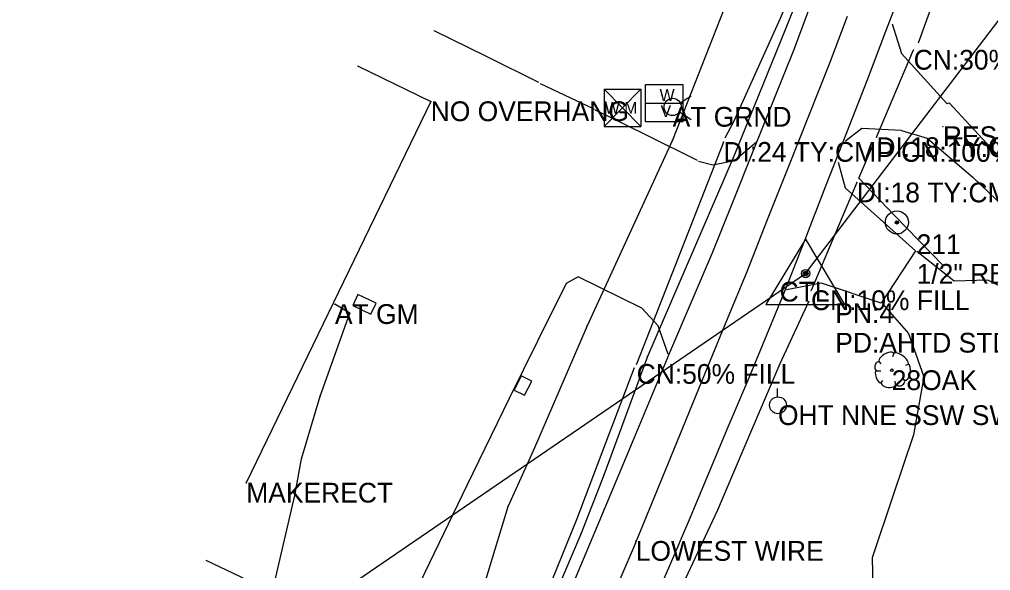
# Model space of a CAD drawing. Extents: x 997398 to 1003416, y 334596 to 337085.
# Drawn here: x 999358.1 to 999603.8, y 336202.6 to 336342 of the extents above; entities that cross this region are included whole.
import ezdxf

# ---------------------------------------------------------------- set-up
doc = ezdxf.new("R2010")
doc.units = 0
for name, color, linetype in [('Default', 7, 'Continuous'), ('S_BUILDING', 7, 'Continuous'), ('S_BUILDING_ANNOT', 7, 'Continuous'), ('S_CURB', 7, 'Continuous'), ('S_DITCHLINE', 7, 'Continuous'), ('S_DRG_PT_SYM', 7, 'Continuous'), ('S_DRIVEWAY', 7, 'Continuous'), ('S_EDGE_CONCRETE', 7, 'Continuous'), ('S_EDGE_PAVEMENT', 7, 'Continuous'), ('S_ELECTRIC_UTILITIES_ANNOT', 7, 'Continuous'), ('S_FIBER_OPTIC_CABLE', 7, 'Continuous'), ('S_GAS_UTILITIES', 7, 'Continuous'), ('S_GAS_UTILITIES_ANNOT', 7, 'Continuous'), ('S_GRAVEL_ROAD', 7, 'Continuous'), ('S_GRD_PT_SYM', 7, 'Continuous'), ('S_IRON_PIN', 7, 'Continuous'), ('S_IRON_PIN_ANNOT', 7, 'Continuous'), ('S_MSC_PT_SYM', 7, 'Continuous'), ('S_PAVEMENT_CROWN', 7, 'Continuous'), ('S_PRIMARY_CTL', 7, 'Continuous'), ('S_PRIMARY_CTL_ANNOT', 7, 'Continuous'), ('S_SIDE_DRAIN', 7, 'Continuous'), ('S_SIDE_DRAIN_ANNOT', 7, 'Continuous'), ('S_STR_PT_SYM', 7, 'Continuous'), ('S_SURVEY_TEXT_ANNOT', 7, 'Continuous'), ('S_TREE', 7, 'Continuous'), ('S_TREE_ANNOT', 7, 'Continuous'), ('S_UTILITY_POLE', 7, 'Continuous'), ('S_UTILITY_POLE_ANNOT', 7, 'Continuous'), ('S_UTL_PT_SYM', 7, 'Continuous'), ('S_WATER_UTILITIES', 7, 'Continuous'), ('S_WATER_UTILITIES_ANNOT', 7, 'Continuous')]:
    doc.layers.add(name, color=color, linetype=linetype)

msp = doc.modelspace()

# ---------------------------------------------------------------- linework, layer by layer
at = {"layer": 'Default'}
for p, q in [((999557.02, 336277.74), (999737.12, 336514.03)), ((998964.3, 335872.43), (999557.02, 336277.74))]:
    msp.add_line(p, q, dxfattribs=at)
at = {"layer": 'S_BUILDING'}
for p, q in [((999443.8, 336330.18), (999462.16, 336321.31)), ((999462.16, 336321.31), (999415.5, 336224.79))]:
    msp.add_line(p, q, dxfattribs=at)
at = {"layer": 'S_CURB'}
for points in [[(999489.52, 336326.12), (999476.27, 336332.64), (999463.01, 336339.16)], [(999529.68, 336306.31), (999527.62, 336307.32), (999510.08, 336316.03), (999504.7, 336318.64), (999503.71, 336319.2)]]:
    msp.add_lwpolyline(points, dxfattribs=at)
at = {"layer": 'S_DITCHLINE'}
for points in [[(999585.56, 336336.15), (999591.87, 336353.69), (999598.19, 336371.23), (999604.53, 336388.73), (999609.68, 336403.37), (999615.75, 336417.57), (999621.81, 336431.76), (999624.66, 336451.18), (999627.5, 336470.6), (999628.27, 336483.98), (999629.05, 336497.37), (999629.83, 336510.76), (999630.6, 336524.14), (999632.81, 336533.43), (999642.82, 336543.03), (999654.22, 336545.64), (999667.32, 336539.63), (999680.41, 336533.63)], [(999569.58, 336389.36), (999561, 336367.01), (999555.79, 336354.64), (999550.58, 336342.27), (999544.69, 336329.2), (999538.8, 336316.12), (999536.54, 336311.97)], [(999591.85, 336279.78), (999579.54, 336292.42), (999570.46, 336301.87), (999574.15, 336310.57)], [(999475.43, 336077.33), (999482.6, 336095.21), (999489.77, 336113.08), (999498.51, 336133.02), (999507.25, 336152.96), (999515.39, 336173.39), (999523.54, 336193.82), (999529.15, 336205.87), (999534.77, 336217.93), (999542.66, 336236.46), (999550.55, 336255), (999557.88, 336270.85)], [(999513.68, 336253.86), (999506.39, 336234.78), (999499.1, 336215.7), (999492.79, 336200.03), (999486.47, 336184.36), (999477.43, 336164.94), (999468.38, 336145.52)]]:
    msp.add_lwpolyline(points, dxfattribs=at)
at = {"layer": 'S_DRG_PT_SYM'}
for points in [[(999584.35, 336334.34), (999584.35, 336334.39), (999584.35, 336334.34), (999584.3, 336334.34), (999584.35, 336334.34), (999584.35, 336334.29), (999584.35, 336334.34), (999584.4, 336334.34)], [(999536.22, 336311.02), (999536.22, 336311.07), (999536.22, 336311.02), (999536.17, 336311.02), (999536.22, 336311.02), (999536.22, 336310.97), (999536.22, 336311.02), (999536.27, 336311.02)], [(999574.93, 336312.22), (999574.93, 336312.27), (999574.93, 336312.22), (999574.88, 336312.22), (999574.93, 336312.22), (999574.93, 336312.17), (999574.93, 336312.22), (999574.98, 336312.22)], [(999569.97, 336300.76), (999569.97, 336300.81), (999569.97, 336300.76), (999569.92, 336300.76), (999569.97, 336300.76), (999569.97, 336300.71), (999569.97, 336300.76), (999570.02, 336300.76)], [(999558.39, 336273.49), (999558.39, 336273.54), (999558.39, 336273.49), (999558.34, 336273.49), (999558.39, 336273.49), (999558.39, 336273.44), (999558.39, 336273.49), (999558.44, 336273.49)], [(999514.27, 336254.84), (999514.27, 336254.89), (999514.27, 336254.84), (999514.22, 336254.84), (999514.27, 336254.84), (999514.27, 336254.79), (999514.27, 336254.84), (999514.33, 336254.84)]]:
    msp.add_lwpolyline(points, dxfattribs=at)
at = {"layer": 'S_DRIVEWAY'}
for points in [[(999578.87, 336340.92), (999581.25, 336333.41), (999592.73, 336320.74)], [(999592.73, 336320.74), (999593.32, 336320.93)], [(999673.98, 336256.32), (999659.54, 336264.21), (999645.1, 336272.09), (999629.83, 336285.07), (999614.55, 336298.06), (999603.94, 336309.49), (999593.32, 336320.93)], [(999581.29, 336313.97), (999571.26, 336314.48), (999567.1, 336311.28)], [(999581.29, 336313.97), (999587.76, 336311.97)], [(999587.76, 336311.97), (999599.44, 336302.01), (999613.16, 336288.85), (999626.87, 336275.69), (999646.61, 336260.45), (999666.35, 336245.21)], [(999565.25, 336305.95), (999567.06, 336299.41), (999584.79, 336283.5), (999576.16, 336270.28), (999561.06, 336275.33), (999552.18, 336273.65)]]:
    msp.add_lwpolyline(points, dxfattribs=at)
at = {"layer": 'S_EDGE_CONCRETE'}
for points in [[(999503.48, 336319.34), (999489.98, 336325.79)], [(999544.56, 336310.96), (999539.05, 336306.25), (999533.56, 336305.19), (999529.93, 336306.12)], [(999522.25, 336257.36), (999519.69, 336264.47), (999515.62, 336268.99), (999499.47, 336276.9), (999496.42, 336275.19), (999489.21, 336260.65), (999482, 336246.12), (999471.33, 336224.11), (999460.67, 336202.1), (999451.61, 336182.6), (999449.32, 336172.31), (999448.89, 336161.32), (999430.05, 336166.38), (999428.87, 336186.15), (999424.48, 336195.98), (999405.32, 336205.16)], [(999446.98, 336267.5), (999448.35, 336270.27), (999443.76, 336272.4), (999442.48, 336269.67)], [(999442.48, 336269.67), (999446.98, 336267.5)], [(999485.89, 336246.94), (999487.74, 336250.5), (999485.03, 336251.89), (999483.31, 336248.27)], [(999483.31, 336248.27), (999485.89, 336246.94)]]:
    msp.add_lwpolyline(points, dxfattribs=at)
at = {"layer": 'S_EDGE_PAVEMENT'}
for points in [[(999462.94, 336067.47), (999472.76, 336088.65), (999482.57, 336109.83), (999487.39, 336121.37), (999492.2, 336132.92), (999497.02, 336144.47), (999501.83, 336156.01), (999507.04, 336167.97), (999512.25, 336179.93), (999517.46, 336191.88), (999522.67, 336203.84), (999527.6, 336215.54), (999532.53, 336227.24), (999537.46, 336238.93), (999542.4, 336250.63), (999551.59, 336272.84), (999556.87, 336286.38), (999562.16, 336299.92), (999567.44, 336313.47), (999572.72, 336327.01), (999577.33, 336339.09), (999581.94, 336351.18)], [(999445.75, 336074.8), (999454.86, 336097.26), (999463.98, 336119.73), (999473.56, 336141.64), (999483.14, 336163.55), (999488.44, 336176.13), (999493.74, 336188.71), (999499.04, 336201.29), (999504.34, 336213.87), (999513.65, 336236.09), (999522.95, 336258.32), (999528.16, 336270.58), (999533.38, 336282.84), (999538.58, 336295.8), (999543.77, 336308.75), (999548.97, 336321.71), (999554.17, 336334.66), (999558.59, 336346.5)]]:
    msp.add_lwpolyline(points, dxfattribs=at)
at = {"layer": 'S_FIBER_OPTIC_CABLE'}
for p, q in [((999536.3, 336344.53), (999523.35, 336311.5)), ((999523.35, 336311.5), (999501.79, 336264.55)), ((999501.79, 336264.55), (999488.19, 336233.05)), ((999488.19, 336233.05), (999481.72, 336218.74)), ((999481.72, 336218.74), (999476.01, 336200.12))]:
    msp.add_line(p, q, dxfattribs=at)
at = {"layer": 'S_GAS_UTILITIES'}
for p, q in [((999562.18, 336365.2), (999551.69, 336338.96)), ((999551.69, 336338.96), (999538.65, 336307.04)), ((999538.65, 336307.04), (999517.04, 336256.78)), ((999441.71, 336267.7), (999437.94, 336269.99)), ((999434.23, 336246.72), (999441.71, 336267.7)), ((999517.04, 336256.78), (999505.93, 336226.75)), ((999429.48, 336230.87), (999434.23, 336246.72)), ((999427.83, 336221.61), (999429.48, 336230.87)), ((999505.93, 336226.75), (999500.19, 336211.79)), ((999420.76, 336191.44), (999427.83, 336221.61)), ((999500.19, 336211.79), (999491.97, 336192.71))]:
    msp.add_line(p, q, dxfattribs=at)
at = {"layer": 'S_GRAVEL_ROAD'}
msp.add_lwpolyline([(999576.51, 336269.96), (999583.04, 336262.6), (999586.9, 336251.61), (999584.32, 336236.92), (999579.09, 336221.38), (999573.87, 336205.84), (999574.11, 336194.28), (999582.9, 336185.79), (999598.73, 336177.31), (999616.12, 336179.59), (999629.75, 336189.17), (999638.84, 336202.7), (999643.92, 336219.19), (999644.25, 336236.84), (999637.21, 336252.76), (999624.04, 336265.72), (999603.11, 336276.06), (999594.63, 336275.8), (999585.12, 336283.33)], dxfattribs=at)
at = {"layer": 'S_GRD_PT_SYM'}
msp.add_lwpolyline([(999514.04, 336210.06), (999514.04, 336210.11), (999514.04, 336210.06), (999513.99, 336210.06), (999514.04, 336210.06), (999514.04, 336210.01), (999514.04, 336210.06), (999514.09, 336210.06)], dxfattribs=at)
at = {"layer": 'S_IRON_PIN'}
for radius in [2.91, 0.411, 0.262, 0.212, 0.145, 0.0822, 0.0581]:
    msp.add_circle((999580.1, 336290.67), radius, dxfattribs=at)
at = {"layer": 'S_MSC_PT_SYM'}
msp.add_lwpolyline([(999591.74, 336314.99), (999591.74, 336315.04), (999591.74, 336314.99), (999591.69, 336314.99), (999591.74, 336314.99), (999591.74, 336314.94), (999591.74, 336314.99), (999591.79, 336314.99)], dxfattribs=at)
at = {"layer": 'S_PAVEMENT_CROWN'}
msp.add_lwpolyline([(999445.27, 336050.62), (999453.51, 336069.51), (999463.26, 336092.28), (999473, 336115.04), (999482.79, 336137.32), (999492.59, 336159.61), (999497.81, 336171.77), (999503.02, 336183.94), (999508.24, 336196.11), (999513.46, 336208.27), (999522.91, 336231.32), (999532.37, 336254.37), (999537.28, 336266.31), (999542.19, 336278.24), (999547.41, 336291.38), (999552.63, 336304.51), (999557.86, 336317.65), (999563.08, 336330.78), (999567.64, 336342.85)], dxfattribs=at)
at = {"layer": 'S_PRIMARY_CTL'}
for p, q in [((999557.02, 336286.44), (999546.99, 336269.93)), ((999557.02, 336286.44), (999566.85, 336269.93)), ((999546.99, 336269.93), (999566.85, 336269.93))]:
    msp.add_line(p, q, dxfattribs=at)
for radius in [1.04, 0.609, 0.344]:
    msp.add_circle((999557.02, 336277.74), radius, dxfattribs=at)
at = {"layer": 'S_SIDE_DRAIN'}
for p, q in [((999574.93, 336312.22), (999584.35, 336334.34)), ((999536.22, 336311.02), (999514.27, 336254.84)), ((999569.97, 336300.76), (999558.39, 336273.49))]:
    msp.add_line(p, q, dxfattribs=at)
at = {"layer": 'S_STR_PT_SYM'}
for points in [[(999443.8, 336330.18), (999443.8, 336330.23), (999443.8, 336330.18), (999443.75, 336330.18), (999443.8, 336330.18), (999443.8, 336330.13), (999443.8, 336330.18), (999443.85, 336330.18)], [(999462.16, 336321.31), (999462.16, 336321.36), (999462.16, 336321.31), (999462.11, 336321.31), (999462.16, 336321.31), (999462.16, 336321.26), (999462.16, 336321.31), (999462.21, 336321.31)], [(999415.5, 336224.79), (999415.5, 336224.84), (999415.5, 336224.79), (999415.45, 336224.79), (999415.5, 336224.79), (999415.5, 336224.74), (999415.5, 336224.79), (999415.55, 336224.79)]]:
    msp.add_lwpolyline(points, dxfattribs=at)
at = {"layer": 'S_TREE'}
for p, q in [((999579.37, 336257.5), (999578.98, 336256.65)), ((999575.57, 336255.49), (999576.07, 336254.91)), ((999582.93, 336254.71), (999582.27, 336254.44)), ((999574.91, 336253.16), (999576.03, 336253.16)), ((999576.07, 336249.99), (999576.54, 336250.68)), ((999579.75, 336249.71), (999579.68, 336250.49)), ((999582.16, 336250.61), (999581.69, 336251.03))]:
    msp.add_line(p, q, dxfattribs=at)
msp.add_circle((999578.81, 336253.26), 0.341, dxfattribs=at)
for centre, major_axis, ratio, start_param, end_param in [((999577.47, 336256.46), (1.86, 1.08), 0.471018, 0, 3.141593), ((999581.13, 336256.14), (-1.81, 1.36), 0.405113, 3.141593, 6.283186), ((999575.24, 336254.35), (0.31, 1.03), 0.646762, 0, 3.141593), ((999582.48, 336252.73), (0.46, 2.04), 0.482994, 3.141593, 6.283185), ((999575.54, 336251.7), (-0.61, 1.6), 0.420543, 6.283185, 9.424777), ((999578, 336249.91), (-1.83, 0.19), 0.529943, 0, 3.141593), ((999580.96, 336250.21), (1.09, 0.46), 0.711534, 3.141592, 6.283185)]:
    msp.add_ellipse(centre, major_axis=major_axis, ratio=ratio, start_param=start_param, end_param=end_param, dxfattribs=at)
at = {"layer": 'S_UTILITY_POLE'}
msp.add_line((999549.9, 336246.55), (999549.9, 336248.66), dxfattribs=at)
msp.add_circle((999550.02, 336244.41), 2.13, dxfattribs=at)
at = {"layer": 'S_UTL_PT_SYM'}
for points in [[(999551.69, 336338.96), (999551.69, 336339.01), (999551.69, 336338.96), (999551.64, 336338.96), (999551.69, 336338.96), (999551.69, 336338.91), (999551.69, 336338.96), (999551.74, 336338.96)], [(999523.35, 336311.5), (999523.35, 336311.55), (999523.35, 336311.5), (999523.3, 336311.5), (999523.35, 336311.5), (999523.35, 336311.45), (999523.35, 336311.5), (999523.4, 336311.5)], [(999538.65, 336307.04), (999538.65, 336307.09), (999538.65, 336307.04), (999538.6, 336307.04), (999538.65, 336307.04), (999538.65, 336306.99), (999538.65, 336307.04), (999538.7, 336307.04)], [(999437.94, 336269.99), (999437.94, 336270.04), (999437.94, 336269.99), (999437.89, 336269.99), (999437.94, 336269.99), (999437.94, 336269.94), (999437.94, 336269.99), (999437.99, 336269.99)], [(999441.71, 336267.7), (999441.71, 336267.75), (999441.71, 336267.7), (999441.66, 336267.7), (999441.71, 336267.7), (999441.71, 336267.65), (999441.71, 336267.7), (999441.76, 336267.7)], [(999501.79, 336264.55), (999501.79, 336264.6), (999501.79, 336264.55), (999501.74, 336264.55), (999501.79, 336264.55), (999501.79, 336264.5), (999501.79, 336264.55), (999501.84, 336264.55)], [(999517.04, 336256.78), (999517.04, 336256.83), (999517.04, 336256.78), (999516.99, 336256.78), (999517.04, 336256.78), (999517.04, 336256.73), (999517.04, 336256.78), (999517.09, 336256.78)], [(999434.23, 336246.72), (999434.23, 336246.77), (999434.23, 336246.72), (999434.18, 336246.72), (999434.23, 336246.72), (999434.23, 336246.67), (999434.23, 336246.72), (999434.28, 336246.72)], [(999488.19, 336233.05), (999488.19, 336233.1), (999488.19, 336233.05), (999488.14, 336233.05), (999488.19, 336233.05), (999488.19, 336233), (999488.19, 336233.05), (999488.24, 336233.05)], [(999429.48, 336230.87), (999429.48, 336230.92), (999429.48, 336230.87), (999429.43, 336230.87), (999429.48, 336230.87), (999429.48, 336230.82), (999429.48, 336230.87), (999429.53, 336230.87)], [(999505.93, 336226.75), (999505.93, 336226.8), (999505.93, 336226.75), (999505.88, 336226.75), (999505.93, 336226.75), (999505.93, 336226.7), (999505.93, 336226.75), (999505.98, 336226.75)], [(999427.83, 336221.61), (999427.83, 336221.66), (999427.83, 336221.61), (999427.78, 336221.61), (999427.83, 336221.61), (999427.83, 336221.56), (999427.83, 336221.61), (999427.88, 336221.61)], [(999481.72, 336218.74), (999481.72, 336218.79), (999481.72, 336218.74), (999481.67, 336218.74), (999481.72, 336218.74), (999481.72, 336218.69), (999481.72, 336218.74), (999481.77, 336218.74)], [(999500.19, 336211.79), (999500.19, 336211.84), (999500.19, 336211.79), (999500.14, 336211.79), (999500.19, 336211.79), (999500.19, 336211.74), (999500.19, 336211.79), (999500.24, 336211.79)], [(999514.04, 336210.06), (999514.04, 336210.11), (999514.04, 336210.06), (999513.99, 336210.06), (999514.04, 336210.06), (999514.04, 336210.01), (999514.04, 336210.06), (999514.09, 336210.06)]]:
    msp.add_lwpolyline(points, dxfattribs=at)
at = {"layer": 'S_WATER_UTILITIES'}
for p, q in [((999516.53, 336325.55), (999525.95, 336325.55)), ((999516.53, 336316.14), (999516.53, 336325.55)), ((999525.95, 336325.55), (999525.95, 336316.14)), ((999506.02, 336324.42), (999515.36, 336324.42)), ((999506.02, 336324.42), (999506.02, 336314.93)), ((999506.02, 336324.42), (999515.36, 336314.93)), ((999515.36, 336324.42), (999506.02, 336314.93)), ((999515.36, 336324.42), (999515.36, 336314.93)), ((999516.53, 336320.87), (999525.95, 336320.87)), ((999525.27, 336320.96), (999528.1, 336322.7)), ((999525.15, 336318.65), (999528.06, 336316.73)), ((999525.95, 336316.14), (999516.53, 336316.14)), ((999506.02, 336314.93), (999515.36, 336314.93))]:
    msp.add_line(p, q, dxfattribs=at)
msp.add_circle((999523.37, 336319.91), 2.18, dxfattribs=at)

# ---------------------------------------------------------------- texts
at = {"layer": 'S_BUILDING_ANNOT'}
for s, p in [('NO OVERHANG', (999462.16, 336316.31)), ('MAKERECT', (999415.5, 336219.79))]:
    msp.add_text(s, height=5, dxfattribs=at).set_placement(p)
at = {"layer": 'S_ELECTRIC_UTILITIES_ANNOT'}
msp.add_text('LOWEST WIRE', height=5, dxfattribs=at).set_placement((999514.04, 336205.06))
at = {"layer": 'S_GAS_UTILITIES_ANNOT'}
msp.add_text('AT GM', height=5, dxfattribs=at).set_placement((999437.94, 336264.99))
at = {"layer": 'S_IRON_PIN_ANNOT'}
for s, p in [('211', (999585.1, 336282.67)), ('1/2" RBR/CAP "JD GARZA 1378"', (999585.1, 336275.17))]:
    msp.add_text(s, height=5, dxfattribs=at).set_placement(p)
at = {"layer": 'S_PRIMARY_CTL'}
msp.add_text('CTL', height=5, rotation=360, dxfattribs=at).set_placement((999550.43, 336270.66))
at = {"layer": 'S_PRIMARY_CTL_ANNOT'}
for s, p in [('PN:4', (999564.52, 336265.24)), ('PD:AHTD STD. MON. STAMPED PN 4', (999564.52, 336257.74))]:
    msp.add_text(s, height=5, dxfattribs=at).set_placement(p)
at = {"layer": 'S_SIDE_DRAIN_ANNOT'}
for s, p in [('CN:30% FILL', (999584.35, 336329.34)), ('DI:24 TY:CMP CN:100% FILL,CRUSH', (999536.22, 336306.02)), ('DI:18 TY:CMP CN:30% FILL', (999574.93, 336307.22)), ('DI:18 TY:CMP CN:4.2% FILL', (999569.97, 336295.76)), ('CN:10% FILL', (999558.39, 336268.49)), ('CN:50% FILL', (999514.27, 336249.84))]:
    msp.add_text(s, height=5, dxfattribs=at).set_placement(p)
at = {"layer": 'S_SURVEY_TEXT_ANNOT'}
msp.add_text('RESIDENCE FRONTING US64', height=5, dxfattribs=at).set_placement((999591.74, 336309.99))
at = {"layer": 'S_TREE_ANNOT'}
msp.add_text('28OAK', height=5, dxfattribs=at).set_placement((999578.81, 336248.26))
at = {"layer": 'S_UTILITY_POLE_ANNOT'}
msp.add_text('OHT NNE SSW SW', height=5, dxfattribs=at).set_placement((999550.02, 336239.41))
at = {"layer": 'S_WATER_UTILITIES'}
for s, p in [('W', (999520.08, 336321.4)), ('W M', (999506.22, 336318.19)), ('V', (999520.32, 336317.33))]:
    msp.add_text(s, height=3, rotation=360, dxfattribs=at).set_placement(p)
at = {"layer": 'S_WATER_UTILITIES_ANNOT'}
msp.add_text('AT GRND', height=5, dxfattribs=at).set_placement((999523.37, 336314.91))

doc.saveas('drawing.dxf')
